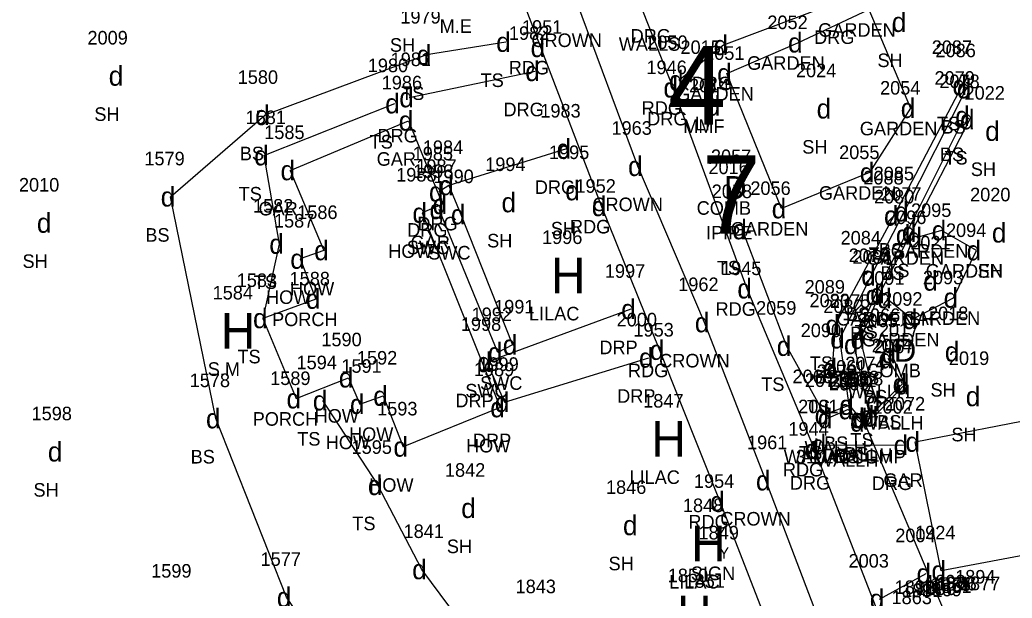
# Model space of a CAD drawing. Extents: x 461160 to 461373, y 202903 to 203086.
# Drawn here: x 461282.4 to 461338, y 203027 to 203059.4 of the extents above; entities that cross this region are included whole.
import ezdxf

# ---------------------------------------------------------------- set-up
doc = ezdxf.new("R2010")
doc.units = 0
for name, color, linetype in [('Level 11', 7, 'Continuous'), ('Level 12', 7, 'Continuous'), ('Level 13', 7, 'Continuous'), ('Level 14', 7, 'Continuous'), ('Level 15', 7, 'Continuous'), ('Level 18', 7, 'Continuous'), ('Level 43', 7, 'Continuous'), ('Level 46', 7, 'Continuous'), ('Level 47', 7, 'Continuous'), ('Level 48', 7, 'Continuous'), ('Level 49', 7, 'Continuous'), ('Level 59', 7, 'Continuous')]:
    doc.layers.add(name, color=color, linetype=linetype)

msp = doc.modelspace()

# ---------------------------------------------------------------- linework, layer by layer
at = {"layer": 'Level 11'}
for points in [[(461337.431, 203004.112), (461335.803, 203008.917), (461333.619, 203019.078), (461330.951, 203025.095), (461326.97, 203035.309), (461323.195, 203044.309), (461319.052, 203055.572), (461315.04, 203065.78), (461311.172, 203077.068)], [(461305.411, 203075.794), (461308.179, 203066.87), (461311.606, 203057.835), (461315.035, 203048.923), (461318.285, 203040.867), (461321.673, 203032.386), (461324.91, 203024.016), (461327.727, 203015.366), (461329.538, 203007.508), (461329.989, 203003.994)], [(461328.21, 203062.88), (461328.721, 203060.543), (461321.865, 203057.949), (461319.365, 203055.979)], [(461304.246, 203055.022), (461311.308, 203056.491)], [(461313.066, 203052.138), (461306.481, 203050.095), (461305.91, 203049.741)], [(461316.683, 203043.157), (461308.611, 203040.182), (461309.598, 203037.942), (461317.681, 203040.434)], [(461327.361, 203035.566), (461331.955, 203035.544)], [(461330.616, 203026.916), (461333.235, 203028.34)]]:
    msp.add_lwpolyline(points, dxfattribs=at)
at = {"layer": 'Level 12'}
for points in [[(461322.062, 203056.369), (461326.035, 203058.094), (461330.017, 203059.947), (461332.352, 203054.423), (461330.058, 203050.812), (461325.12, 203048.8), (461322.062, 203056.369)], [(461306.481, 203050.095), (461307.14, 203048.463), (461310.046, 203041.158), (461309.217, 203040.732), (461305.94, 203048.755)], [(461331.033, 203043.764), (461332.468, 203042.592), (461334.754, 203043.795), (461336.046, 203046.444), (461334.087, 203047.566), (461332.725, 203047.169)], [(461331.277, 203040.682), (461332.033, 203038.931), (461330.292, 203037.128), (461329.509, 203036.847), (461328.867, 203037.538), (461327.704, 203037.039)]]:
    msp.add_lwpolyline(points, dxfattribs=at)
at = {"layer": 'Level 13'}
for points in [[(461297.591, 203050.934), (461304.215, 203053.717), (461306.116, 203049.036), (461304.985, 203048.554), (461309.345, 203037.65), (461303.919, 203035.445)], [(461297.591, 203050.934), (461299.477, 203046.452), (461298.137, 203045.974), (461299.013, 203043.73), (461296.05, 203042.643), (461297.927, 203038.149), (461300.856, 203039.32), (461301.483, 203037.835), (461302.787, 203038.295), (461303.919, 203035.445)], [(461334.073, 203028.503), (461332.617, 203035.719), (461339.916, 203037.142), (461341.321, 203029.861)], [(461341.321, 203029.861), (461334.073, 203028.503)]]:
    msp.add_lwpolyline(points, dxfattribs=at)
at = {"layer": 'Level 48'}
for points in [[(461333.417, 203005.909), (461331.483, 203014.687), (461327.762, 203024.338), (461324.238, 203033.554), (461320.813, 203042.414), (461317.071, 203051.173), (461313.653, 203060.371), (461310.308, 203069.511), (461308.022, 203075.862)], [(461309.677, 203058.129), (461305.224, 203057.405), (461296.168, 203054.025)], [(461309.677, 203058.129), (461305.224, 203057.405), (461296.168, 203054.025)], [(461328.913, 203037.786), (461328.398, 203041.507), (461330.141, 203045.022), (461331.993, 203048.622), (461335.497, 203055.519), (461335.248, 203055.703), (461331.414, 203048.388), (461328.126, 203042.273), (461327.967, 203039.834)], [(461328.913, 203037.786), (461328.398, 203041.507), (461330.141, 203045.022), (461331.993, 203048.622), (461335.497, 203055.519), (461335.248, 203055.703), (461331.414, 203048.388), (461328.126, 203042.273), (461327.967, 203039.834)], [(461296.115, 203051.769), (461303.457, 203054.682)], [(461296.115, 203051.769), (461303.457, 203054.682)], [(461315.541, 203008.651), (461308.105, 203011.488), (461303.992, 203017.318), (461297.386, 203027.014), (461293.414, 203037.031), (461290.876, 203049.461), (461296.168, 203054.025)], [(461315.541, 203008.651), (461308.105, 203011.488), (461303.992, 203017.318), (461297.386, 203027.014), (461293.414, 203037.031), (461290.876, 203049.461), (461296.168, 203054.025)], [(461330.403, 203037.977), (461329.544, 203041.474), (461330.635, 203044.039), (461332.413, 203047.472), (461335.675, 203053.787), (461335.406, 203053.976), (461332.077, 203047.322), (461330.376, 203043.943), (461329.171, 203041.186), (461330.057, 203037.189)], [(461330.403, 203037.977), (461329.544, 203041.474), (461330.635, 203044.039), (461332.413, 203047.472), (461335.675, 203053.787), (461335.406, 203053.976), (461332.077, 203047.322), (461330.376, 203043.943), (461329.171, 203041.186), (461330.057, 203037.189)], [(461296.115, 203051.769), (461296.962, 203046.812), (461296.05, 203042.643)], [(461296.115, 203051.769), (461296.962, 203046.812), (461296.05, 203042.643)], [(461322.916, 203047.625), (461325.405, 203041.091), (461327.526, 203037.252), (461328.913, 203037.786), (461329.521, 203037.051), (461330.057, 203037.189), (461331.898, 203038.981), (461331.103, 203040.393)], [(461322.916, 203047.625), (461325.405, 203041.091), (461327.526, 203037.252), (461328.913, 203037.786), (461329.521, 203037.051), (461330.057, 203037.189), (461331.898, 203038.981), (461331.103, 203040.393)], [(461299.401, 203038.034), (461302.488, 203033.292)], [(461299.401, 203038.034), (461302.488, 203033.292)], [(461321.327, 202988.274), (461324.106, 202992.683), (461325.466, 203002.03), (461321.733, 203002.708), (461316.945, 203004), (461321.225, 203006.69), (461324.085, 203007.39), (461327.398, 203011.243), (461327.047, 203014.732), (461324.41, 203015.108), (461324.41, 203015.108), (461321.477, 203013.865), (461317.057, 203013.221), (461311.718, 203019.474), (461304.97, 203028.576), (461302.488, 203033.292)], [(461321.327, 202988.274), (461324.106, 202992.683), (461325.466, 203002.03), (461321.733, 203002.708), (461316.945, 203004), (461321.225, 203006.69), (461324.085, 203007.39), (461327.398, 203011.243), (461327.047, 203014.732), (461324.41, 203015.108), (461324.41, 203015.108), (461321.477, 203013.865), (461317.057, 203013.221), (461311.718, 203019.474), (461304.97, 203028.576), (461302.488, 203033.292)]]:
    msp.add_lwpolyline(points, dxfattribs=at)
at = {"layer": 'Level 59'}
msp.add_lwpolyline([(461334.565, 203025.496), (461329.672, 203037.032)], dxfattribs=at)

# ---------------------------------------------------------------- texts
at = {"layer": 'Level 14'}
for p in [(461312.2, 203044.052), (461293.7, 203040.944), (461317.831, 203034.885), (461320.057, 203029.026), (461319.271, 203025.098)]:
    msp.add_text('H', height=2, dxfattribs=at).set_placement(p)
at = {"layer": 'Level 15'}
for s, height, p in [('4', 4.4, (461318.751, 203053.502)), ('D', 1.3, (461321.906, 203049.32)), ('D', 1.3, (461331.422, 203040.214))]:
    msp.add_text(s, height=height, dxfattribs=at).set_placement(p)
at = {"layer": 'Level 18'}
msp.add_text('7', height=4.4, dxfattribs=at).set_placement((461320.672, 203047.387))
at = {"layer": 'Level 43'}
msp.add_text('Y', height=0.65, dxfattribs=at).set_placement((461321.611, 203029.171))
at = {"layer": 'Level 46'}
for s, p in [(' M.E  ', (461305.678, 203058.643)), (' DRG  ', (461316.384, 203058.096)), (' DRG  ', (461326.669, 203058.023)), (' GARDEN  ', (461326.894, 203058.427)), (' SH  ', (461302.892, 203057.585)), (' CROWN  ', (461310.823, 203057.851)), (' WALLS  ', (461315.717, 203057.641)), (' RDG  ', (461309.554, 203056.315)), (' GARDEN  ', (461322.912, 203056.574)), (' SH  ', (461330.217, 203056.726)), (' TS  ', (461307.975, 203055.609)), (' DRG  ', (461319.813, 203055.429)), (' TS  ', (461303.522, 203054.885)), (' GARDEN  ', (461318.939, 203054.849)), (' RDG  ', (461317, 203054.052)), (' SH  ', (461286.326, 203053.712)), (' DRG  ', (461309.256, 203053.971)), (' DRG  ', (461317.313, 203053.459)), (' MMF  ', (461319.333, 203053.032)), (' LI  ', (461319.979, 203053.182)), (' TS  ', (461333.546, 203053.183)), (' BS  ', (461333.807, 203052.999)), (' DRG  ', (461302.194, 203052.502)), (' GARDEN  ', (461329.229, 203052.903)), (' TS  ', (461301.755, 203052.162)), (' SH  ', (461326.003, 203051.875)), (' BS  ', (461294.478, 203051.505)), (' BS  ', (461333.716, 203051.456)), (' TS  ', (461333.973, 203051.267)), (' GAR  ', (461302.151, 203051.197)), (' SH  ', (461335.449, 203050.621)), (' DRG  ', (461311.014, 203049.618)), (' TS  ', (461294.413, 203049.249)), (' GARDEN  ', (461326.935, 203049.292)), (' CROWN  ', (461314.241, 203048.653)), (' GAR  ', (461295.527, 203048.414)), (' COMB  ', (461320.085, 203048.45)), (' DRG  ', (461304.429, 203047.575)), (' RDG  ', (461312.983, 203047.403)), (' BS  ', (461289.186, 203046.941)), (' DRG  ', (461303.858, 203047.221)), (' SH  ', (461311.913, 203047.291)), (' IPIPE  ', (461320.607, 203047.067)), (' GARDEN  ', (461321.997, 203047.28)), (' GAR  ', (461304.052, 203046.516)), (' SH  ', (461308.341, 203046.62)), (' HOW  ', (461302.798, 203046.034)), (' SWC  ', (461303.84, 203046.235)), (' SWC  ', (461305.04, 203045.943)), (' TS  ', (461329.712, 203045.868)), (' BS  ', (461330.303, 203046.102)), (' GARDEN  ', (461330.964, 203046.046)), (' SH  ', (461282.3, 203045.471)), (' GARDEN  ', (461329.602, 203045.649)), (' TS  ', (461321.214, 203045.105)), (' BS  ', (461330.387, 203044.802)), (' TS  ', (461330.711, 203044.952)), (' GARDEN  ', (461332.923, 203044.924)), (' SH  ', (461335.825, 203044.923)), (' TS  ', (461295.26, 203044.292)), (' HOW  ', (461297.29, 203043.932)), (' HOW  ', (461295.95, 203043.454)), (' LILAC  ', (461310.687, 203042.532)), (' RDG  ', (461321.143, 203042.789)), (' BS  ', (461328.451, 203042.502)), (' PORCH  ', (461296.288, 203042.21)), (' GARDEN  ', (461327.91, 203042.244)), (' GARDEN  ', (461331.631, 203042.275)), (' SH  ', (461331.978, 203042.228)), (' BS  ', (461328.686, 203041.423)), (' TS  ', (461328.933, 203041.519)), (' GARDEN  ', (461329.345, 203041.072)), (' DRP  ', (461314.631, 203040.637)), (' TS  ', (461294.348, 203040.123)), (' CROWN  ', (461317.983, 203039.894)), (' TS  ', (461326.424, 203039.753)), (' S.M  ', (461292.681, 203039.424)), (' RDG  ', (461316.233, 203039.347)), (' COMB  ', (461329.601, 203039.344)), (' SWC  ', (461307.946, 203038.638)), (' TS  ', (461323.703, 203038.571)), (' BS  ', (461326.708, 203038.987)), (' BS  ', (461327.481, 203038.666)), (' TS  ', (461327.842, 203038.954)), (' SWC  ', (461307.117, 203038.212)), (' DRP  ', (461315.629, 203037.914)), (' WALLH  ', (461328.54, 203038.162)), (' SH  ', (461333.188, 203038.262)), (' DRP  ', (461306.559, 203037.662)), (' BS  ', (461329.413, 203037.873)), (' HOW  ', (461298.669, 203036.8)), (' TS  ', (461326.265, 203037.314)), (' PORCH  ', (461295.202, 203036.629)), (' WALLH  ', (461329.296, 203036.411)), (' BS  ', (461330.208, 203036.461)), (' HOW  ', (461300.6, 203035.775)), (' SH  ', (461334.361, 203035.752)), (' TS  ', (461297.699, 203035.514)), (' HOW  ', (461299.296, 203035.315)), (' HOW  ', (461307.158, 203035.13)), (' DRP  ', (461307.546, 203035.422)), (' BS  ', (461327.223, 203035.266)), (' TS  ', (461328.701, 203035.457)), (' TS  ', (461325.824, 203034.732)), (' WALLH  ', (461326.13, 203035.018)), (' WALLH  ', (461327.555, 203034.608)), (' BS  ', (461328.367, 203034.669)), (' BS  ', (461291.724, 203034.511)), (' WALLH  ', (461324.967, 203034.519)), (' 310ACCGMP  ', (461325.645, 203034.512)), (' WALLH  ', (461326.772, 203034.327)), (' BS  ', (461327.831, 203034.531)), (' RDG  ', (461324.918, 203033.789)), (' HOW  ', (461301.732, 203032.925)), (' LILAC  ', (461316.318, 203033.365)), (' DRG  ', (461325.309, 203033.046)), (' DRG  ', (461329.903, 203033.024)), (' GAR  ', (461330.553, 203033.199)), (' SH  ', (461282.915, 203032.653)), (' TS  ', (461300.786, 203030.772)), (' RDG  ', (461319.621, 203030.866)), (' CROWN  ', (461321.408, 203031.034)), (' SH  ', (461306.083, 203029.488)), (' SH  ', (461315.148, 203028.525)), (' SIGN  ', (461319.758, 203027.976)), (' LILAC  ', (461318.544, 203027.506))]:
    msp.add_text(s, height=0.76, dxfattribs=at).set_placement(p)
at = {"layer": 'Level 47'}
for p in [(461331.303, 203058.696), (461309.127, 203057.579), (461325.485, 203057.544), (461311.056, 203057.285), (461321.315, 203057.399), (461304.674, 203056.855), (461310.758, 203055.941), (461287.412, 203055.682), (461318.815, 203055.429), (461321.512, 203055.819), (461318.502, 203055.022), (461334.698, 203055.153), (461334.947, 203054.969), (461303.696, 203054.472), (461302.907, 203054.132), (461320.877, 203054.002), (461327.089, 203053.845), (461331.802, 203053.873), (461295.618, 203053.475), (461303.665, 203053.167), (461334.856, 203053.426), (461335.125, 203053.237), (461336.535, 203052.591), (461312.516, 203051.588), (461295.565, 203051.219), (461297.041, 203050.384), (461316.521, 203050.623), (461329.508, 203050.262), (461305.931, 203049.545), (461312.999, 203049.261), (461290.326, 203048.911), (461305.36, 203049.191), (461305.39, 203048.205), (461305.566, 203048.486), (461309.427, 203048.59), (461314.485, 203048.373), (461324.57, 203048.25), (461304.435, 203048.004), (461306.59, 203047.913), (461330.864, 203047.838), (461331.443, 203048.072), (461283.386, 203047.441), (461322.366, 203047.075), (461333.537, 203047.016), (461331.527, 203046.772), (461331.863, 203046.922), (461332.175, 203046.619), (461336.911, 203046.893), (461296.412, 203046.262), (461298.927, 203045.902), (461335.496, 203045.894), (461297.587, 203045.424), (461329.591, 203044.472), (461333.064, 203044.198), (461322.645, 203043.759), (461298.463, 203043.18), (461329.826, 203043.393), (461330.085, 203043.489), (461330.483, 203043.214), (461334.204, 203043.245), (461316.133, 203042.607), (461295.5, 203042.093), (461331.918, 203042.042), (461320.263, 203041.864), (461327.576, 203041.723), (461327.848, 203040.957), (461328.994, 203040.924), (461309.496, 203040.608), (461317.735, 203040.317), (461324.855, 203040.541), (461328.621, 203040.636), (461308.667, 203040.182), (461317.131, 203039.884), (461330.553, 203039.843), (461330.727, 203040.132), (461334.274, 203040.232), (461308.061, 203039.632), (461327.417, 203039.284), (461300.306, 203038.77), (461331.348, 203038.431), (461331.483, 203038.381), (461297.377, 203037.599), (461302.237, 203037.745), (461335.447, 203037.722), (461298.851, 203037.484), (461300.933, 203037.285), (461308.795, 203037.1), (461309.048, 203037.392), (461328.317, 203036.988), (461328.363, 203037.236), (461329.853, 203037.427), (461292.864, 203036.481), (461326.976, 203036.702), (461327.154, 203036.489), (461328.971, 203036.501), (461329.122, 203036.482), (461329.507, 203036.639), (461329.742, 203036.578), (461328.959, 203036.297), (461303.369, 203034.895), (461326.42, 203034.759), (461326.811, 203035.016), (461331.405, 203034.994), (461332.067, 203035.169), (461284.001, 203034.623), (461301.938, 203032.742), (461323.688, 203033.004), (461307.169, 203031.458), (461321.123, 203031.836), (461316.234, 203030.495), (461304.42, 203028.026), (461332.685, 203027.79), (461333.523, 203027.953), (461296.836, 203026.464), (461330.066, 203026.366)]:
    msp.add_text('d', height=1.1, dxfattribs=at).set_placement(p)
at = {"layer": 'Level 49'}
for s, p in [(' 1979 ', (461303.477, 203059.165)), (' 1951 ', (461310.293, 203058.595)), (' 2052 ', (461324.046, 203058.854)), (' 2009 ', (461285.94, 203057.992)), (' 1982 ', (461309.564, 203058.251)), (' 2050 ', (461317.313, 203057.739)), (' 2015 ', (461319.177, 203057.462)), (' 2087 ', (461333.259, 203057.463)), (' 2051 ', (461320.504, 203057.129)), (' 2086 ', (461333.469, 203057.279)), (' 1980 ', (461301.65, 203056.442)), (' 1981 ', (461302.933, 203056.782)), (' 1946 ', (461317.269, 203056.332)), (' 1580 ', (461294.361, 203055.785)), (' 2024 ', (461325.65, 203056.155)), (' 2079 ', (461333.414, 203055.736)), (' 1986 ', (461302.432, 203055.477)), (' 2014 ', (461319.653, 203055.312)), (' 2054 ', (461330.363, 203055.183)), (' 2078 ', (461333.686, 203055.547)), (' 2022 ', (461335.096, 203054.901)), (' 1581 ', (461294.802, 203053.529)), (' 1983 ', (461311.322, 203053.898)), (' 1963 ', (461315.309, 203052.933)), (' 1585 ', (461295.847, 203052.694)), (' 1984 ', (461304.737, 203051.855)), (' 1985 ', (461304.166, 203051.501)), (' 1995 ', (461311.805, 203051.571)), (' 2057 ', (461320.883, 203051.347)), (' 2055 ', (461328.069, 203051.572)), (' 1579 ', (461289.129, 203051.221)), (' 1987 ', (461304.372, 203050.796)), (' 1994 ', (461308.233, 203050.9)), (' 2016 ', (461320.743, 203050.73)), (' 1988 ', (461303.241, 203050.314)), (' 1993 ', (461304.196, 203050.515)), (' 1990 ', (461305.333, 203050.223)), (' 2088 ', (461329.425, 203050.148)), (' 2085 ', (461330.004, 203050.382)), (' 2010 ', (461282.099, 203049.751)), (' 1952 ', (461313.291, 203049.683)), (' 2058 ', (461320.927, 203049.385)), (' 2056 ', (461323.092, 203049.56)), (' 2080 ', (461330.025, 203049.082)), (' 2077 ', (461330.424, 203049.232)), (' 2020 ', (461335.409, 203049.203)), (' 1582 ', (461295.218, 203048.572)), (' 1586 ', (461297.694, 203048.212)), (' 2096 ', (461330.697, 203047.929)), (' 2095 ', (461332.098, 203048.326)), (' 1587 ', (461296.393, 203047.734)), (' 1996 ', (461311.417, 203046.812)), (' 2094 ', (461334.057, 203047.204)), (' 2084 ', (461328.152, 203046.782)), (' 2021 ', (461332.056, 203046.508)), (' 2076 ', (461328.607, 203045.799)), (' 2081 ', (461328.818, 203045.703)), (' 1997 ', (461314.939, 203044.917)), (' 1945 ', (461321.451, 203045.069)), (' 1583 ', (461294.306, 203044.403)), (' 1588 ', (461297.269, 203044.49)), (' 1962 ', (461319.051, 203044.174)), (' 2089 ', (461326.134, 203044.033)), (' 2091 ', (461329.475, 203044.524)), (' 2093 ', (461332.765, 203044.555)), (' 1584 ', (461292.956, 203043.704)), (' 1991 ', (461308.733, 203042.918)), (' 2083 ', (461326.409, 203043.267)), (' 2082 ', (461327.182, 203042.946)), (' 2075 ', (461327.555, 203043.234)), (' 2092 ', (461330.479, 203043.352)), (' 1992 ', (461307.473, 203042.492)), (' 2059 ', (461323.413, 203042.851)), (' 2066 ', (461329.231, 203042.442)), (' 2018 ', (461333.05, 203042.542)), (' 1998 ', (461306.867, 203041.942)), (' 2000 ', (461315.599, 203042.194)), (' 2065 ', (461329.096, 203042.153)), (' 1953 ', (461316.541, 203041.627)), (' 2090 ', (461325.915, 203041.594)), (' 2017 ', (461330.298, 203041.624)), (' 1590 ', (461299.049, 203041.08)), (' 2064 ', (461329.891, 203040.741)), (' 2067 ', (461330.026, 203040.691)), (' 1594 ', (461297.657, 203039.794)), (' 1591 ', (461300.17, 203039.595)), (' 1592 ', (461301.043, 203040.055)), (' 1999 ', (461307.851, 203039.702)), (' 2074 ', (461328.414, 203039.737)), (' 2019 ', (461334.22, 203040.032)), (' 1989 ', (461307.598, 203039.41)), (' 2070 ', (461326.815, 203039.298)), (' 2061 ', (461327.337, 203039.546)), (' 1578 ', (461291.67, 203038.791)), (' 1589 ', (461296.18, 203038.909)), (' 2060 ', (461325.456, 203039.012)), (' 2071 ', (461326.146, 203038.799)), (' 2069 ', (461327.499, 203038.607)), (' 2062 ', (461327.514, 203038.811)), (' 1862 ', (461327.91, 203038.792)), (' 2063 ', (461328.05, 203038.949)), (' 2068 ', (461328.285, 203038.888)), (' 1847 ', (461317.087, 203037.645)), (' 2072 ', (461330.628, 203037.479)), (' 1598 ', (461282.807, 203036.933)), (' 1593 ', (461302.175, 203037.205)), (' 2001 ', (461325.773, 203037.326)), (' 2002 ', (461329.936, 203037.304)), (' 1944 ', (461325.226, 203036.069)), (' 1961 ', (461322.907, 203035.314)), (' 1595 ', (461300.744, 203035.052)), (' 1842 ', (461305.975, 203033.768)), (' 1954 ', (461319.929, 203033.146)), (' 1846 ', (461315.001, 203032.805)), (' 1848 ', (461319.313, 203031.786)), (' 1841 ', (461303.657, 203030.336)), (' 1849 ', (461320.189, 203030.256)), (' 1924 ', (461332.329, 203030.263)), (' 2004 ', (461331.216, 203030.1)), (' 1577 ', (461295.642, 203028.774)), (' 2003 ', (461328.597, 203028.676)), (' 1599 ', (461289.511, 203028.116)), (' 1850 ', (461318.464, 203027.858)), (' 1851 ', (461319.404, 203027.545)), (' 1893 ', (461332.9, 203027.509)), (' 1875 ', (461333.196, 203027.369)), (' 1876 ', (461333.518, 203027.4)), (' 1894 ', (461334.571, 203027.783)), (' 1877 ', (461334.838, 203027.411)), (' 1843 ', (461309.935, 203027.242)), (' 1892 ', (461331.178, 203027.201)), (' 1891 ', (461331.597, 203027.022)), (' 1890 ', (461332.374, 203027.139)), (' 1869 ', (461332.688, 203027.067)), (' 1861 ', (461333.234, 203027.256)), (' 1863 ', (461331.006, 203026.63))]:
    msp.add_text(s, height=0.76, dxfattribs=at).set_placement(p)

doc.saveas('drawing.dxf')
